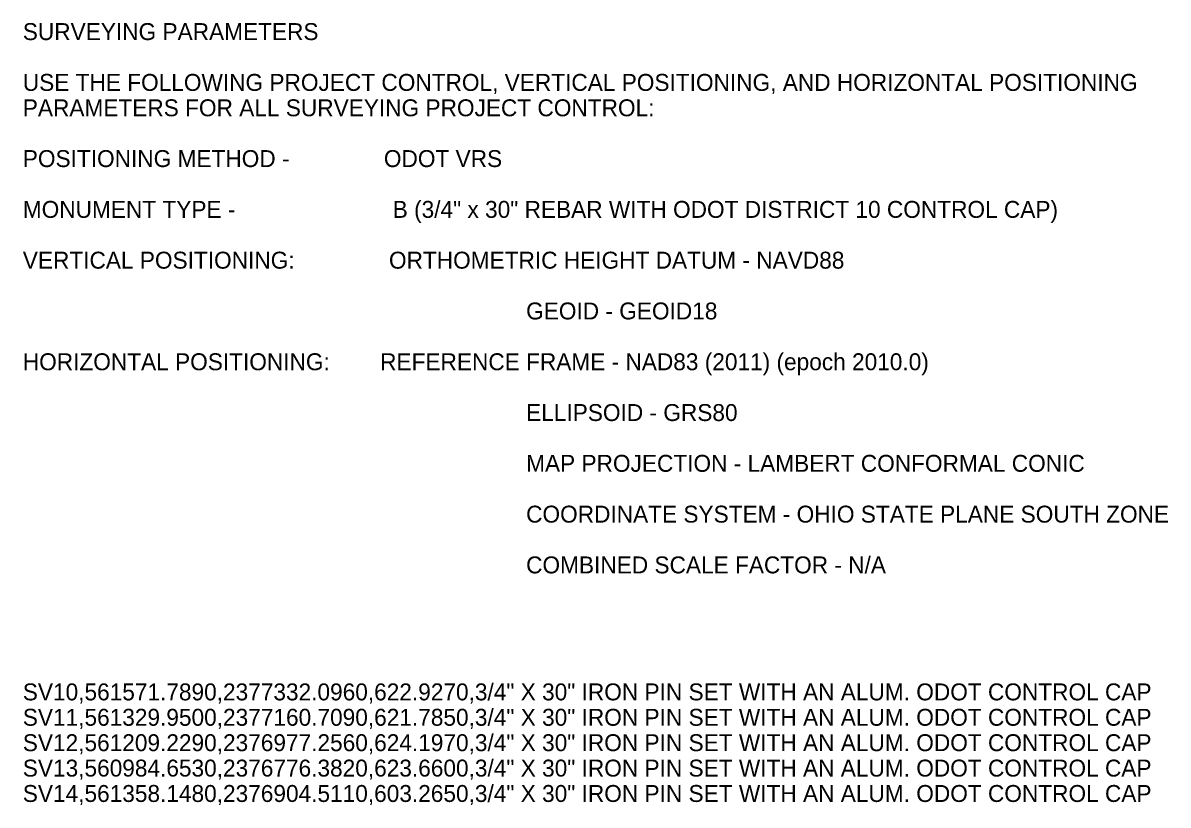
# Model space of a CAD drawing. Extents: x 2376981 to 2378353, y 561188 to 561876.
# Drawn here: x 2377879.9 to 2378353.2, y 561552.6 to 561876 of the extents above; entities that cross this region are included whole.
import ezdxf

# ---------------------------------------------------------------- set-up
doc = ezdxf.new("R2010")
doc.units = 0
doc.layers.add('Default', color=7, linetype='Continuous')

msp = doc.modelspace()

# ---------------------------------------------------------------- texts
at = {"layer": 'Default'}
for s, p in [('SURVEYING PARAMETERS', (2377879.81, 561868.91)), ('USE THE FOLLOWING PROJECT CONTROL, VERTICAL POSITIONING, AND HORIZONTAL POSITIONING', (2377879.81, 561847.91)), ('PARAMETERS FOR ALL SURVEYING PROJECT CONTROL:        ', (2377879.81, 561837.41)), ('POSITIONING METHOD -               ODOT VRS', (2377879.81, 561816.41)), ('MONUMENT TYPE -                         B (3/4" x 30" REBAR WITH ODOT DISTRICT 10 CONTROL CAP)', (2377879.81, 561795.41)), ('VERTICAL POSITIONING:               ORTHOMETRIC HEIGHT DATUM - NAVD88', (2377879.81, 561774.41)), ('                                                                                GEOID - GEOID18', (2377879.81, 561753.41)), ('HORIZONTAL POSITIONING:        REFERENCE FRAME - NAD83 (2011) (epoch 2010.0)', (2377879.81, 561732.41)), ('                                                                                ELLIPSOID - GRS80', (2377879.81, 561711.41)), ('                                                                                MAP PROJECTION - LAMBERT CONFORMAL CONIC', (2377879.81, 561690.41)), ('                                                                                COORDINATE SYSTEM - OHIO STATE PLANE SOUTH ZONE', (2377879.81, 561669.41)), ('                                                                                COMBINED SCALE FACTOR - N/A                                                                                         ', (2377879.81, 561648.41)), ('SV10,561571.7890,2377332.0960,622.9270,3/4" X 30" IRON PIN SET WITH AN ALUM. ODOT CONTROL CAP', (2377879.81, 561595.91)), ('SV11,561329.9500,2377160.7090,621.7850,3/4" X 30" IRON PIN SET WITH AN ALUM. ODOT CONTROL CAP', (2377879.81, 561585.41)), ('SV12,561209.2290,2376977.2560,624.1970,3/4" X 30" IRON PIN SET WITH AN ALUM. ODOT CONTROL CAP', (2377879.81, 561574.91)), ('SV13,560984.6530,2376776.3820,623.6600,3/4" X 30" IRON PIN SET WITH AN ALUM. ODOT CONTROL CAP', (2377879.81, 561564.41)), ('SV14,561358.1480,2376904.5110,603.2650,3/4" X 30" IRON PIN SET WITH AN ALUM. ODOT CONTROL CAP', (2377879.81, 561553.91))]:
    msp.add_text(s, height=7, dxfattribs=at).set_placement(p)

doc.saveas('drawing.dxf')
